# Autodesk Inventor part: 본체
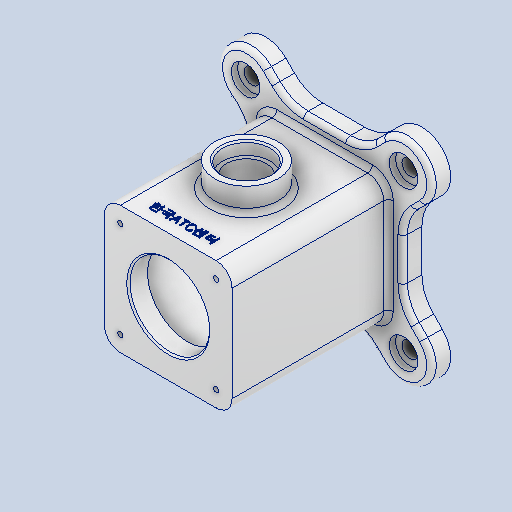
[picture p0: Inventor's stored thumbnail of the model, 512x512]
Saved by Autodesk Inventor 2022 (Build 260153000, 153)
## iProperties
Created: 2022-05
Part Number: 본체
Material: 알루미늄 6061
Document SubType Name: Modeling
Designer: Admin
Mass: 1072.71 g
Surface Area: 877.356 cm^2
Volume: 397.3 cm^3
Density: 2.7 g/cm^3
Appearance: 알루미늄 - 평지
Author: Admin
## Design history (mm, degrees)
sketch "스케치1"
  geometry: L1 (-40, 40)-(40, 40); L2 (40, 40)-(40, -40); L3 (40, -40)-(-40, -40); L4 (-40, -40)-(-40, 40); L5 (-40, 40)-(40, -40); L6 (40, 40)-(-40, -40); 3 further points
  constraints: 12 end point, 3 midpoint, 2 parallel, 1 coincident, 1 horizontal, 1 perpendicular
  dimensions: "d0" = 80 distance of L1.start L1.end; "d1" = 80 distance of L1.end L2.end
extrude "돌출1" new body sketch "스케치1" distance "d2" = 110; taper "d3" = 0 deg
sketch "스케치2"
  geometry: L1 (-49, 49)-(49, 49); L2 (49, 49)-(49, -49); L3 (49, -49)-(-49, -49); L4 (-49, -49)-(-49, 49); L5 (-49, 49)-(49, -49); L6 (49, 49)-(-49, -49); L7 (-61.728, 36.272)-(-49, 23.544); L8 (93.8, 0)-(-93.8, 0) reference; L9 (0, -93.8)-(0, 93.8) reference; L10 (-36.272, 61.728)-(-23.544, 49); L11 (36.272, 61.728)-(23.544, 49); L12 (61.728, 36.272)-(49, 23.544); L13 (-36.272, -61.728)-(-23.544, -49); L14 (-61.728, -36.272)-(-49, -23.544); L15 (36.272, -61.728)-(23.544, -49); L16 (61.728, -36.272)-(49, -23.544); A1 r 18 centre (-49, 49) between (-61.728, 36.272) and (-36.272, 61.728); A2 r 18 centre (49, 49) between (61.728, 36.272) and (36.272, 61.728); A3 r 18 centre (-49, -49) between (-61.728, -36.272) and (-36.272, -61.728); A4 r 18 centre (49, -49) between (61.728, -36.272) and (36.272, -61.728); 9 further points
  constraints: 28 end point, 15 symmetric about line, 8 point on circle, 4 centre point, 4 parallel, 3 midpoint, 2 coincident, 2 point on line, 2 tangent, 1 horizontal, 1 perpendicular, 3 other
  dimensions: "d4" = 98 distance of L1.end L2.end; "d5" = 98 distance of L2.end L3.end; "d6" = 36 diameter of A1
extrude "돌출2" join sketch "스케치2" distance "d7" = 12; taper "d8" = 0 deg
fillet "모깎기1" dims "d9" = 25
sketch "스케치3"
  geometry: L1 (-27, 98)-(3.728, 98) reference; L2 (26.811, 110)-(53.189, 110) reference; C1 r 20 at (40, 49); 3 further points
  constraints: 1 centre point, 1 midpoint, 1 vertical alignment
  dimensions: "d10" = 40 diameter of C1; "d11" = 49 distance from line of L1 C1.centre
extrude "돌출3" join sketch "스케치3" distance "d12" = 15; taper "d13" = 0 deg
node "작업 평면1"
sketch "스케치6"
  geometry: L1 (0, 0)-(0, 110); L2 (40, 110)-(-40, 110) reference; L3 (0, 110)-(25, 110); L4 (25, 98)-(25, 110); L5 (25, 98)-(35, 98); L6 (35, 98)-(35, 12); L7 (35, 12)-(25, 12); L8 (25, 12)-(25, 0); L9 (25, 0)-(0, 0)
  constraints: 16 end point, 5 perpendicular, 1 horizontal, 1 midpoint, 1 point on line
  dimensions: "d15" = 12 distance of L4.start L3.end; "d16" = 12 distance of L7.end L8.end; "d17" = 50 diameter of L4 L1; "d18" = 50 diameter of L8 L1; "d19" = 70 diameter of L6 L1
revolve "회전1" sketch "스케치6" stored, may be unused: angle "d20" = 90 deg
sketch "스케치7"
  geometry: C1 r 20 at (0, 0) reference; C2 r 15 at (0, 0); 1 further point
  constraints: 1 centre point, 1 coincident
  dimensions: "d21" = 30 diameter of C2
extrude "돌출4" cut sketch "스케치7" distance "d22" = 8; taper "d23" = 0 deg
sketch "스케치8"
  geometry: C1 r 15 at (0, 0) reference; C2 r 12.5 at (0, 0); 1 further point
  constraints: 1 centre point, 1 coincident
  dimensions: "d24" = 25 diameter of C2
extrude "돌출5" cut sketch "스케치8" stored distance "d25" = 8; taper "d26" = 0 deg
sketch "스케치9"
  geometry: L1 (-30, 30)-(30, 30); L2 (30, 30)-(30, -30); L3 (30, -30)-(-30, -30); L4 (-30, -30)-(-30, 30); L5 (-30, 30)-(30, -30); L6 (30, 30)-(-30, -30); 7 further points
  constraints: 12 end point, 5 coincident, 3 midpoint, 2 parallel, 1 horizontal, 1 perpendicular
  dimensions: "d27" = 60 distance of L1.end L2.end; "d28" = 60 distance of L1.start L1.end
hole "구멍1" sketch "스케치9" at (-30, 30), (30, 30), (-30, -30), (30, -30) diameter "d29" = 3.242; stored, may be unused: countersink angle "d33" = 90 deg, drill point angle "d35" = 90 deg; dims "d30" = 8, "d31" = 4, "d32" = 2, "d34" = 10
node "작업 평면2"
sketch "스케치12" dims "d38" = 140
  geometry: L1 (0, -98.604)-(0, 101.624) reference; L2 (98, 0)-(-98, 0) reference; L3 (-49.497, 49.497)-(0, 0); C1 r 25 at (0, 0) reference; C2 r 5 at (-49.497, 49.497); C3 r 5 at (49.497, 49.497); C4 r 5 at (-49.497, -49.497); C5 r 5 at (49.497, -49.497); 1 further point
  constraints: 4 centre point, 3 symmetric about line, 2 end point, 1 coincident, 6 other
  dimensions: "d41" = 10 diameter of C2; "d42" = 45 deg angle of L1 L3
extrude "돌출6" cut sketch "스케치12" extent not by distance; stored distance "d43" = 0; taper "d44" = 0 deg
sketch "스케치13"
  geometry: C1 r 5 at (-49.497, 49.497) reference; C2 r 9 at (-49.497, 49.497); C3 r 5 at (49.497, 49.497) reference; C4 r 9 at (49.497, 49.497); C5 r 5 at (-49.497, -49.497) reference; C6 r 9 at (-49.497, -49.497); C7 r 5 at (49.497, -49.497) reference; C8 r 9 at (49.497, -49.497); 1 further point
  constraints: 4 centre point, 4 coincident
  dimensions: "d45" = 18 diameter of C2; "d46" = 18 diameter of C4; "d47" = 18 diameter of C6; "d48" = 18 diameter of C8
extrude "돌출7" cut sketch "스케치13" distance "d49" = 4; taper "d50" = 0 deg
fillet "모깎기2" dims "d51" = 10
fillet "모깎기3" dims "d52" = 3
chamfer "모따기1" distance "d53" = 1; stored, may be unused: second distance "d54" = 2, angle "d55" = 45 deg
sketch "스케치14"
  geometry: L1 (60, 0)-(0, 0) reference; L2 (-10, 95)-(-10, 0) reference; 2 further points
  constraints: 1 other
  dimensions: "d56" = 10 distance from line of L1 point (30, 10); "d57" = 40 distance from line of L2 point (30, 10)
feature "엠보싱1" sketch "스케치14" dims "d4" = 98, "d5" = 98, "d6" = 36, "d58" = 0.5, "d59" = 0
fillet "모깎기4" dims "d60" = 3
node "솔리드1"
mirror "미러1"
feature "A9D066F2-1C7D-4E18-AEED-F7BC21143FA4" dims "d29" = 3.242, "d30" = 8, "d31" = 4, "d32" = 2, "d33" = 90 deg, "d34" = 10, "d35" = 90 deg
other parameters: "d14" = 0, "d36" = -55
